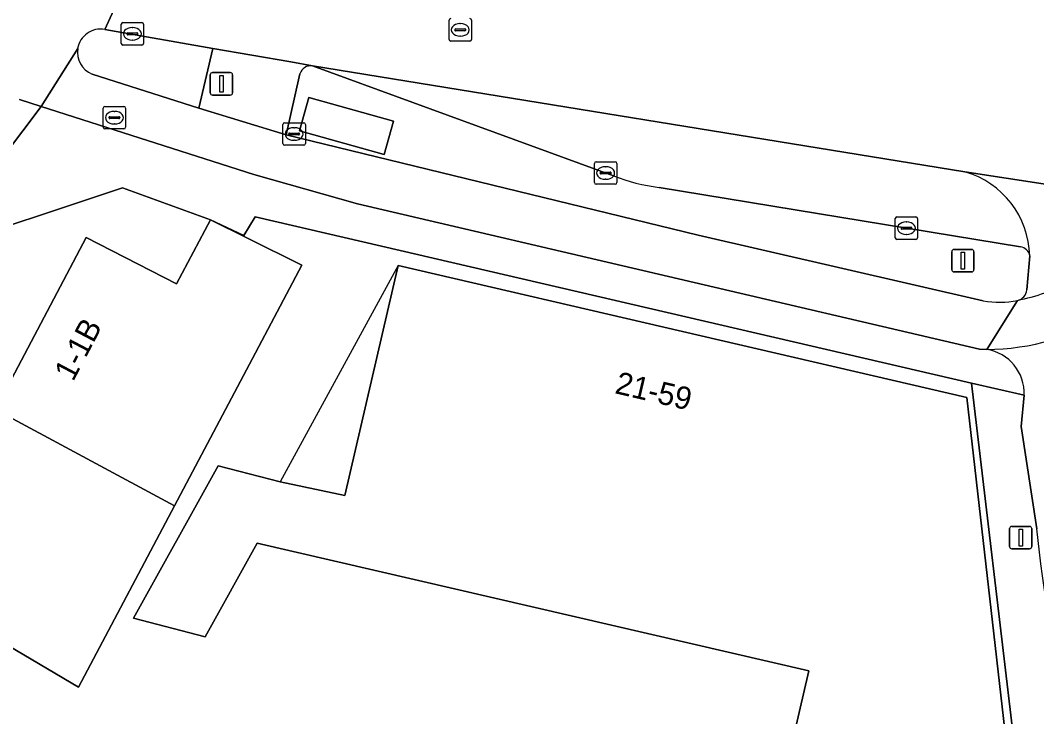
# Model space of a CAD drawing. Extents: x 161771 to 163125, y 382475 to 383179.
# Drawn here: x 161849.5 to 161894.8, y 383111.42 to 383142.48 of the extents above; entities that cross this region are included whole.
import ezdxf

# ---------------------------------------------------------------- set-up
doc = ezdxf.new("R2010")
doc.units = 0
for name, color, linetype in [('IMGEO_Erf', 7, 'Continuous'), ('IMGEO_Fietspad_gesloten', 7, 'Continuous'), ('IMGEO_Kolk', 7, 'Continuous'), ('IMGEO_Lichtmast', 7, 'Continuous'), ('IMGEO_Pand', 7, 'Continuous'), ('IMGEO_Pand_nummerreeks', 7, 'Continuous'), ('IMGEO_Pand_overbouw', 7, 'Continuous'), ('IMGEO_Rijbaan_lokaal_gesloten', 7, 'Continuous'), ('IMGEO_Rijbaan_lokaal_open', 7, 'Continuous'), ('IMGEO_Rioolput', 7, 'Continuous'), ('IMGEO_Verkeerseiland_gesloten', 7, 'Continuous'), ('IMGEO_Verkeersregelinstallatiepaal', 7, 'Continuous'), ('IMGEO_Voetpad_gesloten', 7, 'Continuous'), ('IMGEO_Voetpad_open', 7, 'Continuous')]:
    doc.layers.add(name, color=color, linetype=linetype)

msp = doc.modelspace()

# ---------------------------------------------------------------- linework, layer by layer
at = {"layer": 'IMGEO_Erf'}
for points in [[(161893.776, 383110.359), (161891.895, 383126.294), (161859.967, 383133.719), (161859.465, 383132.882), (161857.966, 383133.582), (161854.053, 383135.016), (161845.553, 383132.186)], [(161882.018, 383102.128), (161884.644, 383113.47), (161860.047, 383119.164), (161857.73, 383114.985), (161854.545, 383115.819), (161858.313, 383122.616), (161861.079, 383121.891), (161863.959, 383121.281), (161866.335, 383131.551), (161891.687, 383125.659), (161893.432, 383110.294)]]:
    msp.add_lwpolyline(points, dxfattribs=at)
msp.add_lwpolyline([(161857.966, 383133.582), (161859.652, 383132.746), (161862.05, 383131.558), (161859.711, 383127.14), (161856.369, 383120.828), (161852.087, 383112.742), (161848.581, 383114.799), (161844.268, 383117.328), (161848.381, 383125.126), (161852.425, 383132.793), (161856.463, 383130.733)], close=True, dxfattribs=at)
at = {"layer": 'IMGEO_Fietspad_gesloten'}
for points in [[(161852.052, 383141.225), (161850.423, 383138.63), (161859.902, 383135.61), (161864.526, 383134.302), (161892.245, 383127.819), (161892.571, 383127.801), (161893.939, 383129.99)], [(161861.339, 383137.377), (161857.449, 383138.559), (161852.692, 383140.086)], [(161892.418, 383129.967), (161879.714, 383132.903), (161861.339, 383137.377)]]:
    msp.add_lwpolyline(points, dxfattribs=at)
for centre, radius, start, end in [((161853.077, 383141.052), 1.04, 170.4087, 248.2543), ((161893.117, 383134.045), 4.137, 260.2727, 281.4599)]:
    msp.add_arc(centre, radius, start, end, dxfattribs=at)
at = {"layer": 'IMGEO_Kolk'}
for p, q in [((161853.99, 383141.453), (161853.99, 383142.305)), ((161854.065, 383142.379), (161854.917, 383142.379)), ((161854.478, 383142.159), (161854.503, 383142.159)), ((161854.991, 383142.305), (161854.991, 383141.453)), ((161854.249, 383141.873), (161854.249, 383141.885)), ((161854.687, 383141.836), (161854.289, 383141.836)), ((161854.292, 383141.922), (161854.69, 383141.922)), ((161854.733, 383141.885), (161854.733, 383141.873)), ((161854.917, 383141.379), (161854.065, 383141.379)), ((161854.501, 383141.599), (161854.476, 383141.599)), ((161861.198, 383136.985), (161861.198, 383137.837)), ((161861.273, 383137.911), (161862.125, 383137.911)), ((161861.686, 383137.691), (161861.711, 383137.691)), ((161862.199, 383137.837), (161862.199, 383136.985)), ((161861.457, 383137.405), (161861.457, 383137.417)), ((161861.895, 383137.368), (161861.497, 383137.368)), ((161861.5, 383137.454), (161861.898, 383137.454)), ((161861.941, 383137.417), (161861.941, 383137.405)), ((161862.125, 383136.911), (161861.273, 383136.911)), ((161861.709, 383137.131), (161861.684, 383137.131)), ((161875.083, 383135.244), (161875.083, 383136.096)), ((161875.158, 383136.17), (161876.01, 383136.17)), ((161875.571, 383135.95), (161875.596, 383135.95)), ((161876.084, 383136.096), (161876.084, 383135.244)), ((161875.342, 383135.664), (161875.342, 383135.676)), ((161875.78, 383135.627), (161875.382, 383135.627)), ((161875.385, 383135.713), (161875.783, 383135.713)), ((161875.594, 383135.39), (161875.569, 383135.39)), ((161875.826, 383135.676), (161875.826, 383135.664)), ((161876.01, 383135.17), (161875.158, 383135.17)), ((161888.49, 383132.785), (161888.49, 383133.637)), ((161888.565, 383133.711), (161889.417, 383133.711)), ((161889.491, 383133.637), (161889.491, 383132.785)), ((161888.749, 383133.205), (161888.749, 383133.217)), ((161889.187, 383133.168), (161888.789, 383133.168)), ((161888.792, 383133.254), (161889.19, 383133.254)), ((161888.978, 383133.491), (161889.003, 383133.491)), ((161889.233, 383133.217), (161889.233, 383133.205)), ((161889.417, 383132.711), (161888.565, 383132.711)), ((161889.001, 383132.931), (161888.976, 383132.931))]:
    msp.add_line(p, q, dxfattribs=at)
for points in [[(161853.99, 383141.453), (161853.99, 383142.305)], [(161854.065, 383142.379), (161854.917, 383142.379)], [(161854.991, 383142.305), (161854.991, 383141.453)], [(161854.917, 383141.379), (161854.065, 383141.379)], [(161861.198, 383136.985), (161861.198, 383137.837)], [(161861.273, 383137.911), (161862.125, 383137.911)], [(161862.199, 383137.837), (161862.199, 383136.985)], [(161862.125, 383136.911), (161861.273, 383136.911)], [(161875.083, 383135.244), (161875.083, 383136.096)], [(161875.158, 383136.17), (161876.01, 383136.17)], [(161876.084, 383136.096), (161876.084, 383135.244)], [(161876.01, 383135.17), (161875.158, 383135.17)], [(161888.49, 383132.785), (161888.49, 383133.637)], [(161888.565, 383133.711), (161889.417, 383133.711)], [(161889.491, 383133.637), (161889.491, 383132.785)], [(161889.417, 383132.711), (161888.565, 383132.711)]]:
    msp.add_lwpolyline(points, dxfattribs=at)
for centre, radius, start, end in [((161854.067, 383142.303), 0.0765, 91.552, 178.448), ((161854.067, 383142.303), 0.0765, 91.552, 178.448), ((161854.915, 383142.303), 0.0765, 1.552, 88.448), ((161854.915, 383142.303), 0.0765, 1.552, 88.448), ((161854.289, 383141.882), 0.0403, 85.8775, 175.7526), ((161854.286, 383141.872), 0.0366, 178.938, 274.7102), ((161854.69, 383141.879), 0.043, 264.8664, 352.4533), ((161854.694, 383141.884), 0.0386, 1.7309, 96.639), ((161854.067, 383141.455), 0.0765, 181.552, 268.448), ((161854.067, 383141.455), 0.0765, 181.552, 268.448), ((161854.915, 383141.455), 0.0765, 271.552, 358.448), ((161854.915, 383141.455), 0.0765, 271.552, 358.448), ((161861.275, 383137.835), 0.0765, 91.552, 178.448), ((161861.275, 383137.835), 0.0765, 91.552, 178.448), ((161862.123, 383137.835), 0.0765, 1.552, 88.448), ((161862.123, 383137.835), 0.0765, 1.552, 88.448), ((161861.497, 383137.414), 0.0403, 85.8775, 175.7526), ((161861.494, 383137.404), 0.0366, 178.938, 274.7102), ((161861.898, 383137.411), 0.043, 264.8664, 352.4533), ((161861.902, 383137.416), 0.0386, 1.7309, 96.639), ((161861.275, 383136.987), 0.0765, 181.552, 268.448), ((161861.275, 383136.987), 0.0765, 181.552, 268.448), ((161862.123, 383136.987), 0.0765, 271.552, 358.448), ((161862.123, 383136.987), 0.0765, 271.552, 358.448), ((161875.16, 383136.094), 0.0765, 91.552, 178.448), ((161875.16, 383136.094), 0.0765, 91.552, 178.448), ((161876.008, 383136.094), 0.0765, 1.552, 88.448), ((161876.008, 383136.094), 0.0765, 1.552, 88.448), ((161875.382, 383135.673), 0.0403, 85.8775, 175.7526), ((161875.379, 383135.663), 0.0366, 178.938, 274.7102), ((161875.783, 383135.67), 0.043, 264.8664, 352.4533), ((161875.787, 383135.675), 0.0386, 1.7309, 96.639), ((161875.16, 383135.246), 0.0765, 181.552, 268.448), ((161875.16, 383135.246), 0.0765, 181.552, 268.448), ((161876.008, 383135.246), 0.0765, 271.552, 358.448), ((161876.008, 383135.246), 0.0765, 271.552, 358.448), ((161888.567, 383133.635), 0.0765, 91.552, 178.448), ((161888.567, 383133.635), 0.0765, 91.552, 178.448), ((161889.415, 383133.635), 0.0765, 1.552, 88.448), ((161889.415, 383133.635), 0.0765, 1.552, 88.448), ((161888.789, 383133.214), 0.0403, 85.8775, 175.7526), ((161888.786, 383133.204), 0.0366, 178.938, 274.7102), ((161889.19, 383133.211), 0.043, 264.8664, 352.4533), ((161889.194, 383133.216), 0.0386, 1.7309, 96.639), ((161888.567, 383132.787), 0.0765, 181.552, 268.448), ((161888.567, 383132.787), 0.0765, 181.552, 268.448), ((161889.415, 383132.787), 0.0765, 271.552, 358.448), ((161889.415, 383132.787), 0.0765, 271.552, 358.448)]:
    msp.add_arc(centre, radius, start, end, dxfattribs=at)
for centre, major_axis, ratio, start_param, end_param in [((161854.477, 383141.879), (-0.387, 0.002), 0.722429, 4.712389, 7.853982), ((161854.502, 383141.879), (-0.39, 0.002), 0.717154, 1.570796, 4.712389), ((161861.685, 383137.411), (-0.387, 0.002), 0.722429, 4.712389, 7.853982), ((161861.71, 383137.411), (-0.39, 0.002), 0.717154, 1.570796, 4.712389), ((161875.57, 383135.67), (-0.387, 0.002), 0.722429, 4.712389, 7.853982), ((161875.595, 383135.67), (-0.39, 0.002), 0.717154, 1.570796, 4.712389), ((161888.977, 383133.211), (-0.387, 0.002), 0.722429, 4.712389, 7.853982), ((161889.002, 383133.211), (-0.39, 0.002), 0.717154, 1.570796, 4.712389)]:
    msp.add_ellipse(centre, major_axis=major_axis, ratio=ratio, start_param=start_param, end_param=end_param, dxfattribs=at)
at = {"layer": 'IMGEO_Lichtmast'}
for p, q in [((161891.011, 383131.36), (161891.011, 383132.16)), ((161891.011, 383132.16), (161891.011, 383131.36)), ((161891.111, 383132.26), (161891.901, 383132.26)), ((161891.901, 383132.26), (161891.111, 383132.26)), ((161892.001, 383132.16), (161892.001, 383131.36)), ((161892.001, 383131.36), (161892.001, 383132.16)), ((161891.901, 383131.26), (161891.111, 383131.26)), ((161891.111, 383131.26), (161891.901, 383131.26)), ((161893.589, 383119.009), (161893.589, 383119.809)), ((161893.589, 383119.809), (161893.589, 383119.009)), ((161893.689, 383119.909), (161894.479, 383119.909)), ((161894.479, 383119.909), (161893.689, 383119.909)), ((161894.579, 383119.809), (161894.579, 383119.009)), ((161894.579, 383119.009), (161894.579, 383119.809)), ((161894.479, 383118.909), (161893.689, 383118.909)), ((161893.689, 383118.909), (161894.479, 383118.909))]:
    msp.add_line(p, q, dxfattribs=at)
for points in [[(161891.431, 383132.135), (161891.581, 383132.135), (161891.581, 383131.385), (161891.431, 383131.385), (161891.431, 383132.135)], [(161894.009, 383119.784), (161894.159, 383119.784), (161894.159, 383119.034), (161894.009, 383119.034), (161894.009, 383119.784)]]:
    msp.add_lwpolyline(points, dxfattribs=at)
for centre, start, end in [((161891.111, 383132.16), 90, 180), ((161891.111, 383132.16), 90, 180), ((161891.901, 383132.16), 0, 90), ((161891.901, 383132.16), 360, 90), ((161891.111, 383131.36), 180, 270), ((161891.111, 383131.36), 180, 270), ((161891.901, 383131.36), 270, 0), ((161891.901, 383131.36), 270, 0), ((161893.689, 383119.809), 90, 180), ((161893.689, 383119.809), 90, 180), ((161894.479, 383119.809), 0, 90), ((161894.479, 383119.809), 360, 90), ((161893.689, 383119.009), 180, 270), ((161893.689, 383119.009), 180, 270), ((161894.479, 383119.009), 270, 0), ((161894.479, 383119.009), 270, 0)]:
    msp.add_arc(centre, 0.1, start, end, dxfattribs=at)
at = {"layer": 'IMGEO_Pand'}
for points in [[(161862.05, 383131.558), (161859.652, 383132.746), (161857.966, 383133.582), (161856.463, 383130.733), (161852.425, 383132.793), (161848.381, 383125.126), (161856.369, 383120.828), (161859.711, 383127.14)], [(161882.018, 383102.128), (161894.113, 383103.934), (161893.432, 383110.294), (161891.687, 383125.659), (161866.335, 383131.551), (161863.959, 383121.281), (161861.079, 383121.891), (161858.313, 383122.616), (161854.545, 383115.819), (161857.73, 383114.985), (161860.047, 383119.164), (161884.644, 383113.47)], [(161848.381, 383125.126), (161844.268, 383117.328), (161848.581, 383114.799), (161852.087, 383112.742), (161856.369, 383120.828)]]:
    msp.add_lwpolyline(points, close=True, dxfattribs=at)
at = {"layer": 'IMGEO_Pand_overbouw'}
msp.add_lwpolyline([(161861.079, 383121.891), (161863.959, 383121.281), (161866.335, 383131.551)], close=True, dxfattribs=at)
at = {"layer": 'IMGEO_Rijbaan_lokaal_gesloten'}
for points in [[(161974.777, 383123.907), (161931.625, 383134.527), (161927.938, 383135.419), (161921.093, 383137.145), (161918.999, 383137.683), (161904.911, 383141.086), (161865.575, 383149.78), (161864.206, 383150.074), (161862.232, 383150.497), (161860.286, 383150.918), (161857.589, 383151.53), (161853.259, 383142.074), (161858.074, 383141.224), (161861.557, 383140.632), (161862.515, 383140.445), (161891.594, 383135.723), (161906.528, 383133.437), (161909.255, 383133.02), (161917.154, 383131.486), (161937.858, 383126.382), (161955.16, 383122.046)], [(161853.259, 383142.074), (161857.589, 383151.53)], [(161849.452, 383138.944), (161850.423, 383138.63), (161852.052, 383141.225)], [(161904.043, 383133.294), (161906.528, 383133.437), (161891.594, 383135.723)], [(161894.49, 383131.976), (161894.362, 383130.459)], [(161893.939, 383129.99), (161892.571, 383127.801)]]:
    msp.add_lwpolyline(points, dxfattribs=at)
for centre, radius, start, end in [((161853.078, 383141.048), 1.042, 80.015, 170.2298), ((161890.469, 383131.861), 4.023, 1.6449, 73.7549), ((161892.305, 383138.212), 8.382, 281.2401, 298.5711), ((161892.305, 383138.212), 8.382, 281.2401, 298.5711), ((161893.833, 383130.51), 0.531, 281.463, 354.4412), ((161892.497, 383138.36), 10.56, 270.4019, 301.9765)]:
    msp.add_arc(centre, radius, start, end, dxfattribs=at)
at = {"layer": 'IMGEO_Rijbaan_lokaal_open'}
for points in [[(161862.515, 383140.445), (161875.938, 383135.541)], [(161891.594, 383135.723), (161862.515, 383140.445)], [(161877.967, 383135.025), (161894.071, 383132.375)], [(161894.232, 383125.758), (161894.106, 383124.369), (161894.796, 383119.807)]]:
    msp.add_lwpolyline(points, dxfattribs=at)
for centre, radius, start, end in [((161879.058, 383143.561), 8.605, 248.7442, 262.7187), ((161890.469, 383131.861), 4.023, 1.6449, 73.7549), ((161894.016, 383131.898), 0.48, 9.3586, 83.4426), ((161892.497, 383138.36), 10.56, 270.4019, 301.9765), ((161892.275, 383125.864), 1.96, 356.9024, 81.3212), ((161945.388, 383124.557), 50.815, 185.3632, 194.8819)]:
    msp.add_arc(centre, radius, start, end, dxfattribs=at)
at = {"layer": 'IMGEO_Rioolput'}
for p, q in [((161868.604, 383141.629), (161868.604, 383142.481)), ((161869.092, 383142.335), (161869.117, 383142.335)), ((161869.605, 383142.481), (161869.605, 383141.629)), ((161868.863, 383142.049), (161868.863, 383142.061)), ((161869.301, 383142.012), (161868.903, 383142.012)), ((161868.906, 383142.098), (161869.304, 383142.098)), ((161869.115, 383141.775), (161869.09, 383141.775)), ((161869.347, 383142.061), (161869.347, 383142.049)), ((161869.531, 383141.555), (161868.679, 383141.555)), ((161853.189, 383137.713), (161853.189, 383138.565)), ((161853.264, 383138.639), (161854.116, 383138.639)), ((161854.19, 383138.565), (161854.19, 383137.713)), ((161853.448, 383138.133), (161853.448, 383138.145)), ((161853.886, 383138.096), (161853.488, 383138.096)), ((161853.491, 383138.182), (161853.889, 383138.182)), ((161853.677, 383138.419), (161853.702, 383138.419)), ((161853.932, 383138.145), (161853.932, 383138.133)), ((161854.116, 383137.639), (161853.264, 383137.639)), ((161853.7, 383137.859), (161853.675, 383137.859))]:
    msp.add_line(p, q, dxfattribs=at)
for points in [[(161868.604, 383141.629), (161868.604, 383142.481)], [(161869.605, 383142.481), (161869.605, 383141.629)], [(161869.531, 383141.555), (161868.679, 383141.555)], [(161853.189, 383137.713), (161853.189, 383138.565)], [(161853.264, 383138.639), (161854.116, 383138.639)], [(161854.19, 383138.565), (161854.19, 383137.713)], [(161854.116, 383137.639), (161853.264, 383137.639)]]:
    msp.add_lwpolyline(points, dxfattribs=at)
for centre, radius, start, end in [((161868.681, 383142.479), 0.0765, 91.552, 178.448), ((161868.681, 383142.479), 0.0765, 91.552, 178.448), ((161869.529, 383142.479), 0.0765, 1.552, 88.448), ((161869.529, 383142.479), 0.0765, 1.552, 88.448), ((161868.903, 383142.058), 0.0403, 85.8775, 175.7526), ((161868.9, 383142.048), 0.0366, 178.938, 274.7102), ((161869.304, 383142.055), 0.043, 264.8664, 352.4533), ((161869.308, 383142.06), 0.0386, 1.7309, 96.639), ((161868.681, 383141.631), 0.0765, 181.552, 268.448), ((161868.681, 383141.631), 0.0765, 181.552, 268.448), ((161869.529, 383141.631), 0.0765, 271.552, 358.448), ((161869.529, 383141.631), 0.0765, 271.552, 358.448), ((161853.266, 383138.563), 0.0765, 91.552, 178.448), ((161853.266, 383138.563), 0.0765, 91.552, 178.448), ((161854.114, 383138.563), 0.0765, 1.552, 88.448), ((161854.114, 383138.563), 0.0765, 1.552, 88.448), ((161853.488, 383138.142), 0.0403, 85.8775, 175.7526), ((161853.485, 383138.132), 0.0366, 178.938, 274.7102), ((161853.889, 383138.139), 0.043, 264.8664, 352.4533), ((161853.893, 383138.144), 0.0386, 1.7309, 96.639), ((161853.266, 383137.715), 0.0765, 181.552, 268.448), ((161853.266, 383137.715), 0.0765, 181.552, 268.448), ((161854.114, 383137.715), 0.0765, 271.552, 358.448), ((161854.114, 383137.715), 0.0765, 271.552, 358.448)]:
    msp.add_arc(centre, radius, start, end, dxfattribs=at)
for centre, major_axis, ratio, start_param, end_param in [((161869.091, 383142.055), (-0.387, 0.002), 0.722429, 4.712389, 7.853982), ((161869.116, 383142.055), (-0.39, 0.002), 0.717154, 1.570796, 4.712389), ((161853.676, 383138.139), (-0.387, 0.002), 0.722429, 4.712389, 7.853982), ((161853.701, 383138.139), (-0.39, 0.002), 0.717154, 1.570796, 4.712389)]:
    msp.add_ellipse(centre, major_axis=major_axis, ratio=ratio, start_param=start_param, end_param=end_param, dxfattribs=at)
at = {"layer": 'IMGEO_Verkeerseiland_gesloten'}
msp.add_lwpolyline([(161852.692, 383140.086), (161857.449, 383138.559), (161858.074, 383141.224), (161853.259, 383142.074)], dxfattribs=at)
for centre, radius, start, end in [((161853.078, 383141.048), 1.042, 80.015, 170.2298), ((161853.077, 383141.052), 1.04, 170.4087, 248.2543)]:
    msp.add_arc(centre, radius, start, end, dxfattribs=at)
at = {"layer": 'IMGEO_Verkeersregelinstallatiepaal'}
for p, q in [((161857.963, 383139.248), (161857.963, 383140.048)), ((161857.963, 383140.048), (161857.963, 383139.248)), ((161858.063, 383140.148), (161858.853, 383140.148)), ((161858.853, 383140.148), (161858.063, 383140.148)), ((161858.953, 383140.048), (161858.953, 383139.248)), ((161858.953, 383139.248), (161858.953, 383140.048)), ((161858.853, 383139.148), (161858.063, 383139.148)), ((161858.063, 383139.148), (161858.853, 383139.148))]:
    msp.add_line(p, q, dxfattribs=at)
msp.add_lwpolyline([(161858.383, 383140.023), (161858.533, 383140.023), (161858.533, 383139.273), (161858.383, 383139.273), (161858.383, 383140.023)], dxfattribs=at)
for centre, start, end in [((161858.063, 383140.048), 90, 180), ((161858.063, 383140.048), 90, 180), ((161858.853, 383140.048), 0, 90), ((161858.853, 383140.048), 360, 90), ((161858.063, 383139.248), 180, 270), ((161858.063, 383139.248), 180, 270), ((161858.853, 383139.248), 270, 0), ((161858.853, 383139.248), 270, 0)]:
    msp.add_arc(centre, 0.1, start, end, dxfattribs=at)
at = {"layer": 'IMGEO_Voetpad_gesloten'}
msp.add_lwpolyline([(161866.132, 383137.984), (161862.352, 383139.044), (161861.935, 383137.557), (161865.715, 383136.497)], close=True, dxfattribs=at)
at = {"layer": 'IMGEO_Voetpad_open'}
for points in [[(161862.515, 383140.445), (161861.557, 383140.632), (161858.074, 383141.224), (161857.449, 383138.559), (161861.339, 383137.377), (161861.96, 383140.092)], [(161875.938, 383135.541), (161862.515, 383140.445)], [(161861.96, 383140.092), (161861.339, 383137.377), (161879.714, 383132.903), (161892.418, 383129.967)], [(161845.553, 383132.186), (161850.423, 383138.63), (161849.452, 383138.944)], [(161859.902, 383135.61), (161850.423, 383138.63), (161845.553, 383132.186), (161854.053, 383135.016), (161857.966, 383133.582), (161859.465, 383132.882), (161859.967, 383133.719), (161891.895, 383126.294), (161894.232, 383125.758)], [(161892.571, 383127.801), (161892.245, 383127.819), (161864.526, 383134.302), (161859.902, 383135.61)], [(161894.071, 383132.375), (161877.967, 383135.025)], [(161894.362, 383130.459), (161894.49, 383131.976)], [(161894.796, 383119.807), (161894.106, 383124.369), (161894.232, 383125.758), (161891.895, 383126.294), (161893.776, 383110.359), (161893.432, 383110.294), (161894.113, 383103.934), (161894.772, 383104.032), (161899.195, 383093.413), (161904.523, 383080.621), (161903.225, 383076.749), (161904.748, 383075.23), (161905.674, 383075.8)]]:
    msp.add_lwpolyline(points, dxfattribs=at)
msp.add_lwpolyline([(161865.715, 383136.497), (161861.935, 383137.557), (161862.352, 383139.044), (161866.132, 383137.984)], close=True, dxfattribs=at)
for centre, radius, start, end in [((161862.436, 383139.957), 0.494, 80.7611, 164.1545), ((161862.436, 383139.957), 0.494, 80.7611, 164.1545), ((161879.058, 383143.561), 8.605, 248.7442, 262.7187), ((161894.016, 383131.898), 0.48, 9.3586, 83.4426), ((161893.833, 383130.51), 0.531, 281.463, 354.4412), ((161893.117, 383134.045), 4.137, 260.2727, 281.4599), ((161892.275, 383125.864), 1.96, 356.9024, 81.3212), ((161945.388, 383124.557), 50.815, 185.3632, 194.8819)]:
    msp.add_arc(centre, radius, start, end, dxfattribs=at)

# ---------------------------------------------------------------- texts
at = {"layer": 'IMGEO_Pand_nummerreeks'}
for s, rotation, p in [('1-1B', 62.1888, (161851.846, 383126.336)), ('21-59', 346.8656, (161875.953, 383125.855))]:
    msp.add_text(s, height=1, rotation=rotation, dxfattribs=at).set_placement(p)

doc.saveas('drawing.dxf')
